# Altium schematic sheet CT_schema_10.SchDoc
size 147 x 119 mm
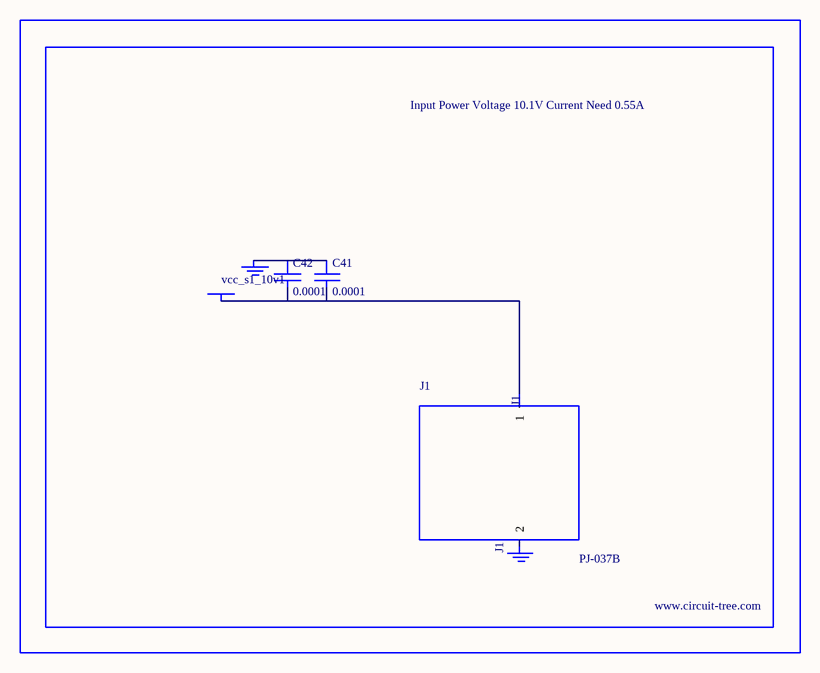
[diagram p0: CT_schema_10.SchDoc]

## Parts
BORDER9  (no value)
C41  0.0001  [EXV-9H]
C42  0.0001  [EXV-9H]
GND_INSTANCE_9_0  (no value)
GND_INSTANCE_9_1  (no value)
J1  PJ-037B  [PJ-037B_PACKAGE]
POWER_INSTANCE_9_0  vcc_s1_10v1

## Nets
NetC41_1: C41.1 C42.1 GND_INSTANCE_9_0.0(GND)
NetC41_2: C41.2 C42.2 J1.1 POWER_INSTANCE_9_0.0(PWR)

Not connected (* = marked no-connect by the designer): GND_INSTANCE_9_1 0(GND); J1 2

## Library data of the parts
BORDER9 = BORDER_PAGE9
C41 C42 = EDK107M035A9HAA
GND_INSTANCE_9_0 GND_INSTANCE_9_1 = GND
POWER_INSTANCE_9_0 = PWR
